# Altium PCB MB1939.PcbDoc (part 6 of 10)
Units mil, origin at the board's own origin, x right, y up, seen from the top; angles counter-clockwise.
Board outline 5910.64 x 4335.93 mil, 6 copper layers (Top Layer, l2_GND, L3_SIG, L4_VCC, L5_GND, Bottom Layer), stack 58.424 mil thick; 635 components, 489 nets, 2289 pads, 1388 vias.
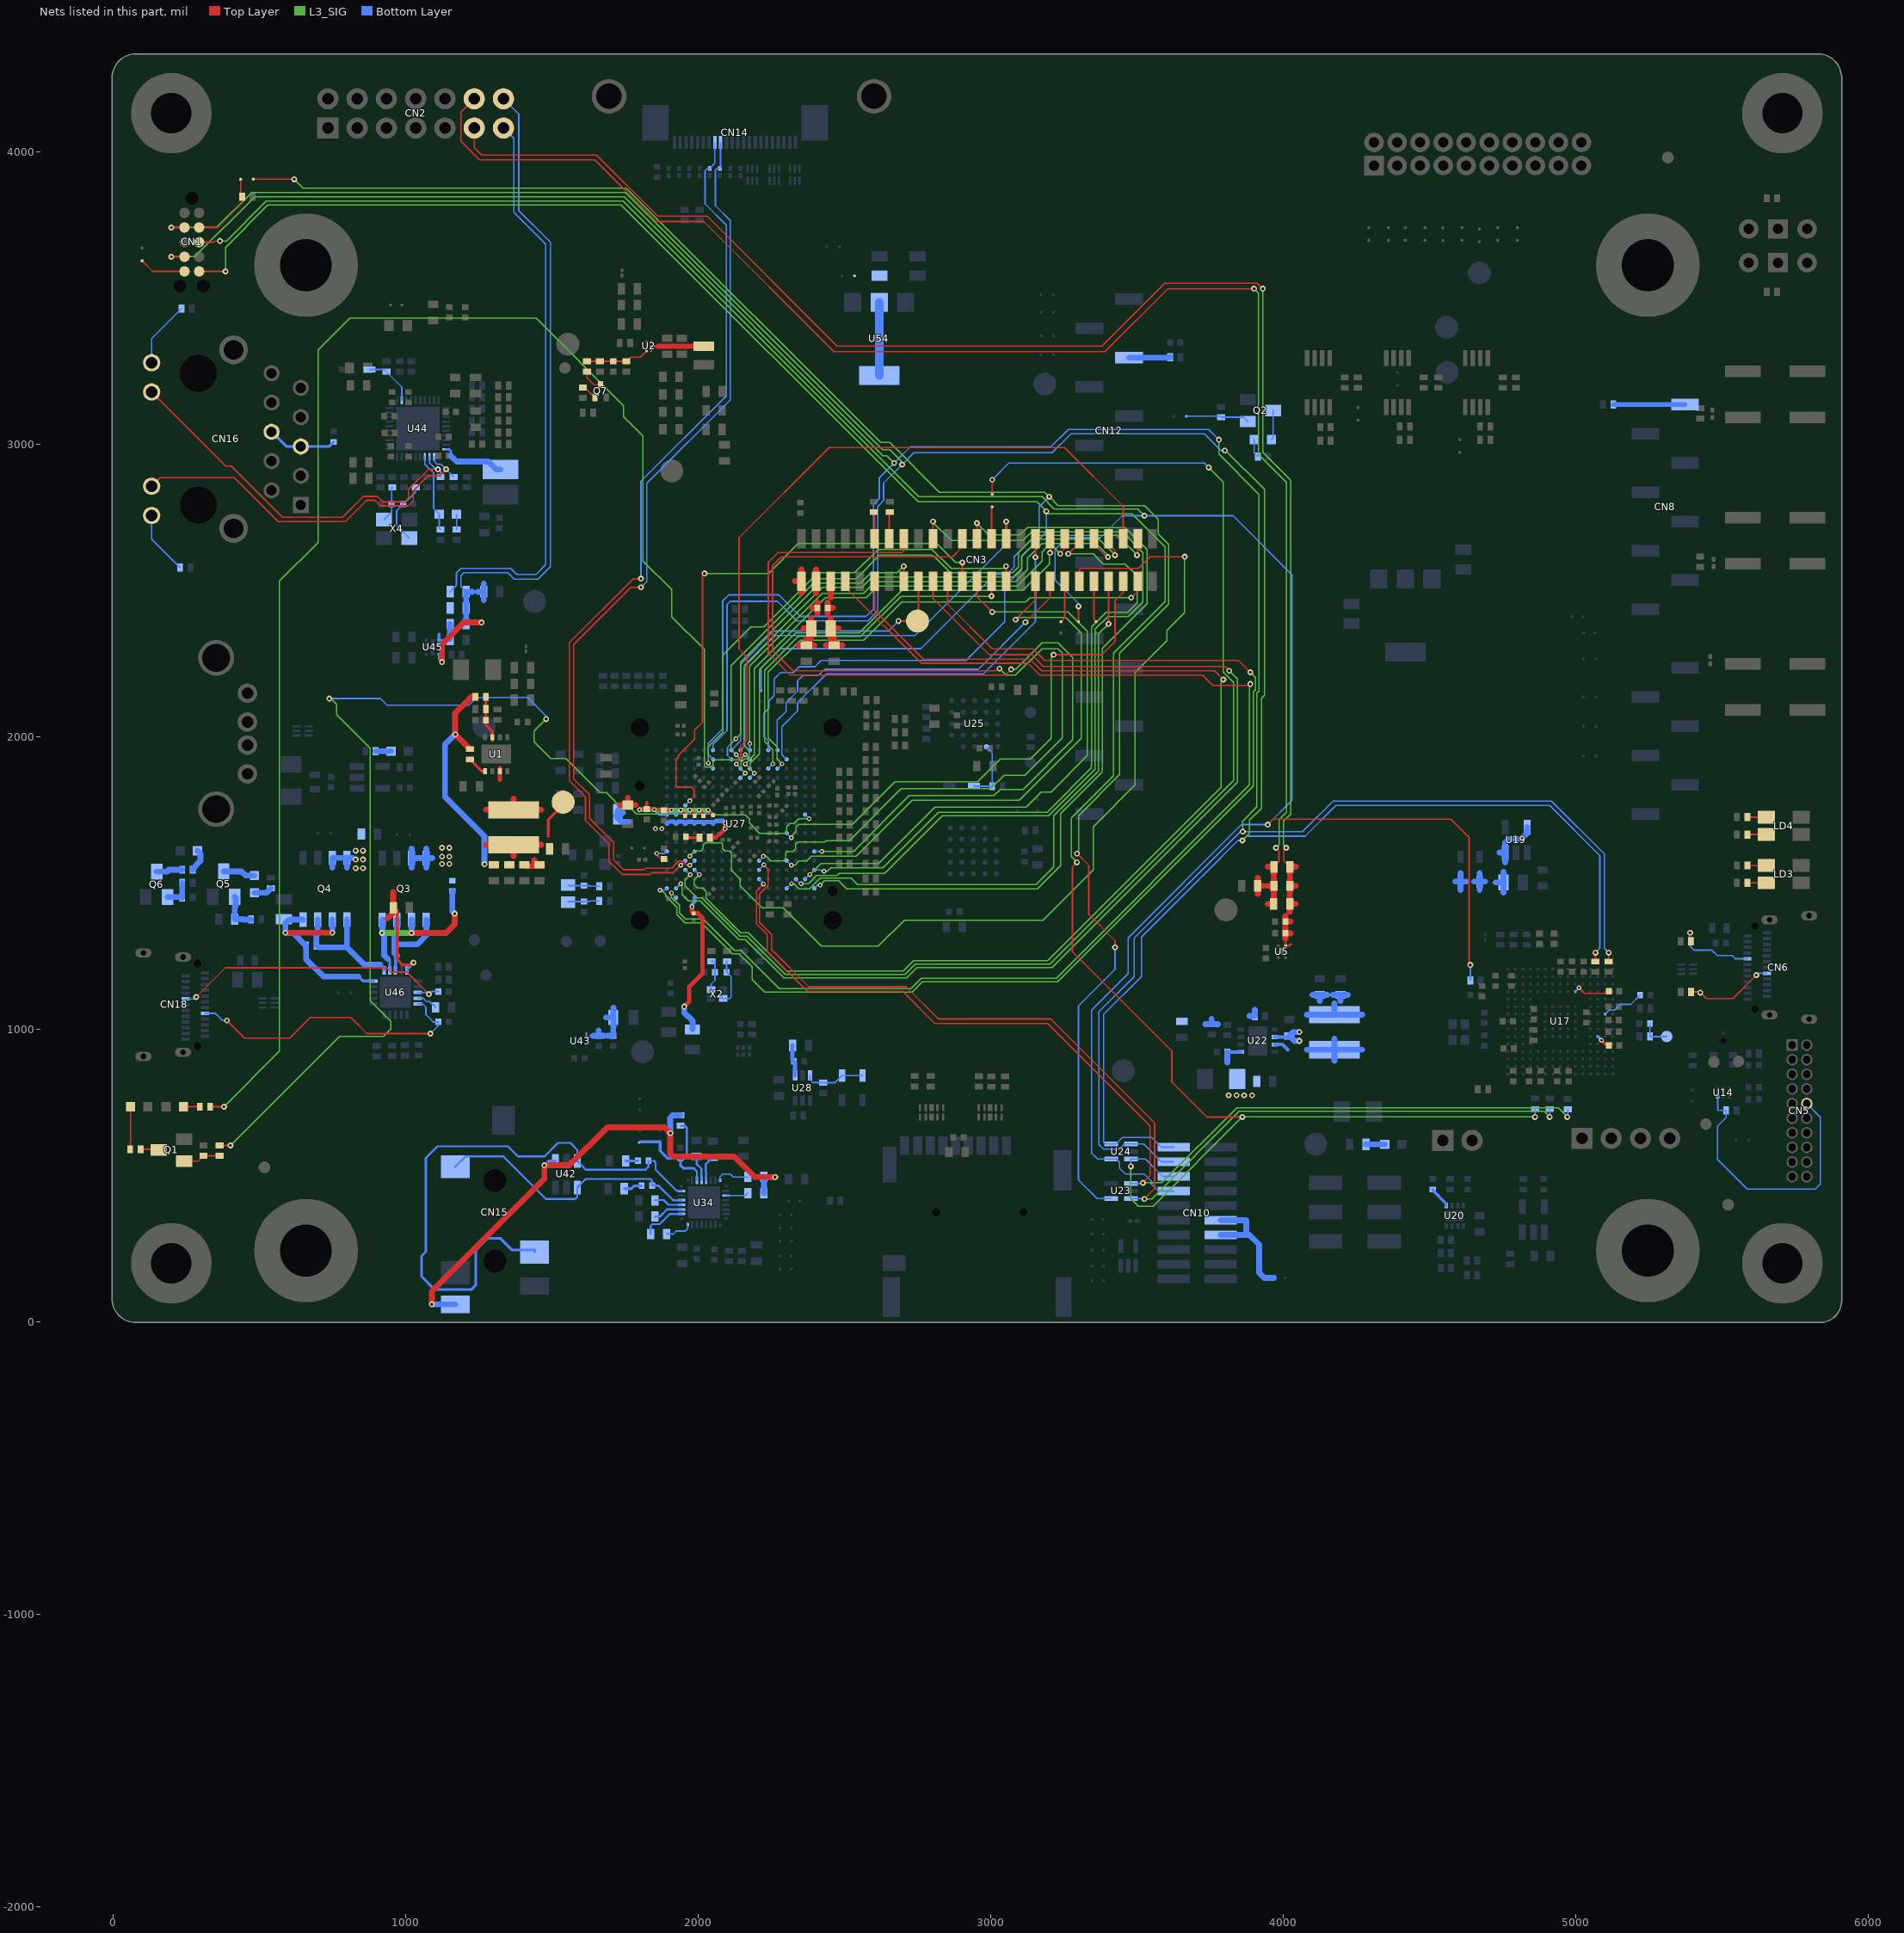
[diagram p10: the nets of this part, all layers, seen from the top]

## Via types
v1: diameter 20, hole 10, Top Layer to Bottom Layer, tented both sides, 1072 vias
v2: diameter 16, hole 8, Top Layer to Bottom Layer, tented both sides, 316 vias

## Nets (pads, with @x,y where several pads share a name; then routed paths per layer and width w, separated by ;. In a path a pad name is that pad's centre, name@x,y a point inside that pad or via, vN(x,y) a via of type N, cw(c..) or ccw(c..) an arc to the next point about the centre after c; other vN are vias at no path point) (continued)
I_SENS_VDDA1V8_N: C182.1 CN2.14 R179.1 R187.2 R188.2 U45.4 | length 2500.7
  Top Layer w20: v1(1125,2255) 1125,2316.08 1198.92,2390 v1(1260,2390)
  Bottom Layer w5: R188.2@1207.56,2495 1190,2512.56 1190,2550 1200,2560 1350,2560 1371.6,2538.4 1453,2538.4 1495,2580.4 1495,3690 1387.1,3797.9 1387.1,4127.9 CN2.14@1335,4180
  Bottom Layer w8: U45.4@1115.2,2281.57 1115.2,2264.8 v1(1125,2255)
  Bottom Layer w20: C182.1@1207.56,2402.29 R187.2@1207.56,2457.71 ; 1207.56,2467.29 R188.2@1207.56,2495 1228.18,2495 ; 1246.82,2495 R179.1@1267.45,2495 ; 1267.44,2467.29 R179.1@1267.45,2495 ; 1267.44,2522.71 R179.1@1267.45,2495
I_SENS_VDDA1V8_P: C182.2 C183.2 CN2.13 R187.1 R188.1 U45.1 U45.2 | length 2061.6
  Bottom Layer w5: R188.1@1152.45,2495 1174,2516.56 1174,2559 1190,2575 1360,2575 1380.3,2554.7 1446,2554.7 1479,2587.7 1479,3683.37 1370.28,3792.09 1370.28,4044.72 CN2.13@1335,4080
  Bottom Layer w7: U45.2@1115.2,2313.06 1131.91,2313.06
  Bottom Layer w10: 1115.19,2349.81 U45.1@1115.2,2328.81 1128.81,2328.81 1130,2330
  Bottom Layer w20: C183.2@1152.44,2335 C182.2@1152.45,2385
I_SENS_VDDIO_N: C93.1 CN2.12 R78.1 R79.2 R80.2 | length 5552.3
  Top Layer w5: CN2.12@1235,4180 1190,4135 1190,4035 1253.19,3971.81 1646.56,3971.81 1857.82,3760.55 2019.45,3760.55 2464.17,3315.83 3390.83,3315.83 3605.82,3530.82 v1(3900,3530.82) ; R80.2@3967.45,1555 3985,1572.56 3985,1610 v1(3975,1620)
  Top Layer w20: 3912.56,1462.29 R78.1@3912.56,1490 ; 3912.56,1517.71 R78.1@3912.56,1490 ; 3933.18,1490 R78.1@3912.56,1490 ; 3946.31,1427.99 R79.2@3966.94,1427.99 3966.93,1455.7 ; 3946.82,1490 C93.1@3967.45,1490 ; 3946.82,1555 R80.2@3967.45,1555 3967.44,1527.29 ; 3967.44,1464.46 C93.1@3967.45,1490 ; 3967.44,1515.54 C93.1@3967.45,1490
  L3_SIG w4: v1(3900,3530.82) 3915,3515.82 3915,2965.2 3940,2940.2 3940,2938.78 4010,2868.78 4010,1741.22 3985,1716.22 3985,1630 v1(3975,1620)
I_SENS_VDDIO_P: C93.2 C94.2 C95.2 CN2.11 R79.1 R80.1 U5.1 | length 5523.5
  Top Layer w5: CN2.11@1235,4080 1235,4012.63 1259.82,3987.81 1653.19,3987.81 1862.42,3778.58 2031.42,3778.58 2475,3335 3380,3335 3595,3550 3910.82,3550 v1(3930,3530.82) ; v1(4010,1620) 4007.49,1620 4001.49,1614 4001.49,1576.07 R80.1@4022.56,1555
  Top Layer w8: 4007.8,1297.8 U5.1@4007.8,1285.27 4020.28,1285.28 4025,1290
  Top Layer w20: 4007.21,1308.94 C94.2@4007.21,1327.99 ; 4007.21,1347.04 C94.2@4007.21,1327.99 ; 4007.21,1348.94 C95.2@4007.21,1367.99 ; 4007.21,1387.04 C95.2@4007.21,1367.99 ; 4022.05,1400.28 R79.1@4022.05,1427.99 ; 4022.05,1455.7 R79.1@4022.05,1427.99 ; 4022.56,1464.46 C93.2@4022.56,1490 ; 4022.56,1515.54 C93.2@4022.56,1490 ; 4022.56,1527.29 R80.1@4022.56,1555 4043.18,1555 ; 4025.27,1327.99 C94.2@4007.21,1327.99 ; 4025.27,1367.99 C95.2@4007.21,1367.99 ; 4042.67,1427.99 R79.1@4022.05,1427.99 ; 4043.18,1490 C93.2@4022.56,1490
  L3_SIG w4: v1(3930,3530.82) 3930,2971.27 4025,2876.27 4025,1735 4000,1710 4000,1630 v1(4010,1620)
IMU_INT1: CN14.14 U27.E4 U36.1 | length 3099.5
  Top Layer w5: v1(1805,2510) 1770,2510 1575,2315 1575,1855.44 1629,1801.44 1629,1721 1711.78,1638.22 1711.78,1579 1745.78,1545 1815,1545 1820,1550 1909.77,1550 1934.59,1574.82 1946.61,1574.82 1961.11,1560.32 v2(1972.1,1560.32)
  Bottom Layer w5: v1(1805,2510) 1825,2530 1825,2866 2109.5,3150.5 2109.5,3764.52 2059.02,3815 2059.02,3936.32 2065,3942.3 U36.1@2075,3942.31 2077.09,3944.39 CN14.14@2077.09,4030.71 ; v2(1972.1,1560.32) U27.E4@1987.81,1576.03
IMU_INT2: CN14.15 U27.E3 U37.1 | length 3097.7
  Top Layer w5: v1(1805,2540) 1778.78,2540 1560,2321.22 1560,1849.22 1615,1794.22 1615,1714 1695.78,1633.22 1695.78,1573.78 1740.56,1529 1834,1529 1840,1535 1915.28,1535 v2(1940.6,1560.32)
  Bottom Layer w5: v1(1805,2540) 1805,2873 2096.5,3164.5 2096.5,3748.5 2024.02,3820.98 2024.02,3934.02 2032.3,3942.3 U37.1@2040,3942.31 2057.4,3959.7 CN14.15@2057.41,4030.71 ; v2(1940.6,1560.32) 1956.31,1576.03 U27.E3@1956.37,1576.03
JNTRST: SB2.2 SB43.1 U23.4 | length 7593
  Top Layer w5: SB2.2@480.02,3905 v1(620,3905) ; v1(3295,1600) 3335,1560 3335,1392.5 3425,1302.5 v1(3425,1280)
  L3_SIG w4: v1(620,3905) 650,3875 1754.04,3875 2624.04,3005 2655,3005 2825,2835 3185,2835 v1(3200,2820) 3230,2790 3525,2790 3572,2743 3572,2693 3608,2657 3608,2453.01 3441,2286.01 3441,1871 3300,1730 3300,1605 v1(3295,1600)
  Bottom Layer w5: SB43.1@2215,2157.72 2215,2231.92 2283.88,2300.8 2760.8,2300.8 3015,2555 3055,2555 3080,2580 3080,2615 3165,2700 3165,2785 v1(3200,2820) ; U23.4@3412.05,421.42 3363.58,421.42 3300,485 3300,1080 3425,1205 v1(3425,1280)
LCD_B0: CN3.21 U27.R6 | length 1614.6
  Top Layer w5: v1(3052.5,2582.5) 3052.87,2582.13 CN3.21@3052.87,2531.12
  L3_SIG w4: v2(2035.01,1909.5) 2035.01,1965.01 2085,2015 2085,2280 2180,2375 2225,2375 2410,2560 2535,2560 2615,2640 2800,2640 2865,2575 3045,2575 v1(3052.5,2582.5)
  Bottom Layer w5: v2(2035.01,1909.5) 2035.01,1906.69 2050.71,1890.99 U27.R6@2050.86,1890.99
LCD_B1: CN3.23 U27.R12 | length 1286.1
  Top Layer w5: v1(3002.87,2480) CN3.23@3002.87,2531.12
  L3_SIG w4: v2(2255.48,1906.76) 2255.48,1954.75 2227,1983.23 2227,2227 2341.2,2341.2 2344.22,2341.2 2345.02,2342 2555.19,2342 2693.19,2480 v1(3002.87,2480)
  Bottom Layer w5: U27.R12@2239.84,1890.99 2255.48,1906.64 v2(2255.48,1906.76)
LCD_B2: CN3.25 U27.C16 | length 2043.1
  Top Layer w5: CN3.25@2952.87,2531.12 2952.87,2478.13 v1(3005,2426)
  L3_SIG w4: v2(2381.48,1528.79) 2419.69,1567 2617,1567 2809,1759 3120.99,1759 3173,1811.01 3206.01,1811.01 3330,1935 3330,2360 3264,2426 v1(3005,2426)
  Bottom Layer w5: U27.C16@2365.82,1513.03 2365.82,1513.13 v2(2381.48,1528.79)
LCD_B3: CN3.27 U27.L3 | length 1912.4
  Top Layer w5: v2(1972,1780.63) 1987,1795.63 1987,1816.73 1976.12,1827.61 1930,1827.61 1924.7,1832.91 1924.7,1920.62 1932.53,1928.45 1932.53,1935.53 1988,1991 1988,2021.99 2015,2048.99 2015,2550.5 v1(2022.1,2557.6) ; CN3.27@2902.87,2531.12 v1(2902.87,2595)
  L3_SIG w4: v1(2022.1,2557.6) 2240.4,2557.6 2342.8,2660 2815,2660 2880,2595 v1(2902.87,2595)
  Bottom Layer w5: U27.L3@1956.37,1765 v2(1972,1780.63)
LCD_B4: CN3.29 U27.B1 | length 4141.1
  Top Layer w5: CN3.29@2852.87,2531.12 2852.87,2452.13 3005,2300 3145,2300 3185,2260 3847,2260 v1(3887,2220)
  L3_SIG w4: v2(1869.89,1475.41) 1874.36,1475.41 1888.95,1460.82 1888.95,1456.05 1928,1417 1928,1392 1956,1364 2012,1364 2118,1258 2140,1258 2185,1213 2185,1170 2228,1127 2732,1127 2767.59,1162.59 3229.22,1162.59 3897,1830.37 3897,2152.95 3905,2160.95 3905,2202 v1(3887,2220)
  Bottom Layer w5: v2(1869.89,1475.41) 1870,1475.52 1887.36,1475.52 U27.B1@1893.38,1481.54
LCD_B5: CN3.31 U27.B2 | length 3920.4
  Top Layer w5: CN3.31@2802.87,2531.12 2802.87,2472.13 2995,2280 3140,2280 3180,2240 3800,2240 v1(3815,2225)
  L3_SIG w4: v2(1940.5,1497.26) 1945,1492.76 1945,1460.01 1967.01,1438 2007.01,1438 2139.01,1306 2162,1306 2293,1175 2711.99,1175 2747.58,1210.59 3209.3,1210.59 3843,1844.29 3843,2197 v1(3815,2225)
  Bottom Layer w5: U27.B2@1924.88,1481.54 1924.87,1481.63 v2(1940.5,1497.26)
LCD_B6: CN3.33 TP1.1 U27.U8 | length 1109.8
  Top Layer w5: v1(2685,2395) TP1.1@2750,2395 2752.87,2397.87 CN3.33@2752.87,2531.12
  Bottom Layer w5: U27.U8@2113.85,1953.98 2145,1985.13 2145,2093.89 2145.03,2209.04 2145.03,2247.47 2257.86,2360.3 2258.5,2360.3 2259,2360.8 2650.8,2360.8 v1(2685,2395)
LCD_B7: CN3.35 U27.T8 | length 1101.1
  Top Layer w5: CN3.35@2702.87,2531.12 v1(2702.87,2582.13)
  L3_SIG w4: v2(2129.5,1993.1) 2144.62,2008.22 2144.62,2254.62 2415,2525 2555,2525 2590,2560 2680.74,2560 v1(2702.87,2582.13)
  Bottom Layer w5: U27.T8@2113.85,1922.48 2100.2,1936.13 2100.2,1963.8 v2(2129.5,1993.1)
LCD_BL_CTRL: CN3.43 U27.A2 | length 4337.1
  Top Layer w5: CN3.43@2502.87,2531.12 2502.87,2510.91 2762.78,2251 3126.56,2251 3167.56,2210 3724,2210 3759,2175 3880,2175 3885,2180 v1(3887,2180)
  L3_SIG w4: v2(1909.02,1465.8) 1909.02,1450.98 1936.5,1423.5 1936.5,1397.5 1957,1377 2017,1377 2124,1270 2147.06,1270 2278.06,1139 2726.93,1139 2762.52,1174.59 3224.24,1174.59 3885,1835.35 3885,2178 v1(3887,2180)
  Bottom Layer w5: v2(1909.02,1465.8) 1924.78,1450.04 U27.A2@1924.88,1450.04
LCD_CLK: CN3.32 U27.C15 | length 2886.9
  Top Layer w5: CN3.32@2802.87,2676.22 v1(2802.87,2735)
  L3_SIG w4: v2(2351.9,1497.3) 2376.96,1497.3 2404.66,1525 2475,1525 2483,1533 2638,1533 2835,1730 3198.02,1730 3356,1887.98 3356,1895.01 3356.97,1895.98 3356.97,1902.97 ; v1(2802.87,2735) 2802.87,2732.13 2865,2670 3110,2670 3140,2700 3450,2700 3520,2630 3520,2460 3470,2410 3400,2410 3357,2367 3357,1903
  Bottom Layer w5: U27.C15@2334.33,1513.03 2350.02,1497.3 v2(2351.9,1497.3)
LCD_DE: CN3.22 U27.U9 | length 1494.9
  Top Layer w5: CN3.22@3052.87,2676.22 v1(3052.87,2735)
  Bottom Layer w5: U27.U9@2145.35,1953.98 2160,1968.64 2160,2087.67 2160.03,2209.03 2160.03,2241.25 2259.08,2340.3 2259.72,2340.3 2265.22,2345.8 2741.2,2345.8 3052.87,2657.47 v1(3052.87,2735)
LCD_G0: CN3.4 U27.T9 | length 2070.2
  Top Layer w5: v1(3500,2620) 3502.87,2622.87 CN3.4@3502.87,2676.22
  L3_SIG w4: v2(2130.62,1938.6) 2112.6,1956.62 2112.6,2242.6 2410,2540 2540,2540 2620,2620 2800,2620 2805,2615 2808.02,2615 2863.02,2560 3075,2560 3095,2580 3095,2630.01 3152.99,2688 3432,2688 v1(3500,2620)
  Bottom Layer w5: v2(2130.62,1938.6) 2130.62,1937.14 U27.T9@2145.35,1922.48 U27.T9@2145.35,1922.48
LCD_G1: CN3.6 U27.R9 | length 2456
  Top Layer w5: v2(2130.26,1906.07) 2146,1921.81 2146,1968.9 2167.12,1990.02 2167.12,2272.12 2140,2299.24 2140,2680 2447.67,2987.67 3252.33,2987.67 3452.87,2787.13 CN3.6@3452.87,2676.22
  Bottom Layer w5: v2(2130.26,1906.07) U27.R9@2145.35,1890.99
LCD_G2: CN3.8 U27.P9 | length 1979.5
  Top Layer w5: CN3.8@3402.87,2676.22 3402.87,2657.13 3425,2635 v1(3425,2620)
  L3_SIG w4: v2(2160.99,1875.27) 2146.8,1889.46 2146.8,1912.54 2158.39,1924.13 2166.87,1924.13 2175.07,1932.33 2175.07,1951.62 2156.62,1970.07 2156.62,2238.6 2160,2241.98 2160,2245 2425,2510 2560,2510 2595,2545 3076.98,2545 3107,2575.02 3107,2617 3165,2675 3370,2675 v1(3425,2620)
  Bottom Layer w5: U27.P9@2145.35,1859.49 2145.34,1859.62 v2(2160.99,1875.27)
LCD_G3: CN3.10 U27.U10 | length 1815.5
  Top Layer w5: CN3.10@3352.87,2676.22 3352.87,2657.14 3396.08,2613.93 v1(3400.74,2613.93)
  L3_SIG w4: v2(2176.78,1976.01) 2176.78,2241.78 2425,2490 2565,2490 2605,2530 3085,2530 3125,2570 3125,2610 3175,2660 3360,2660 3400.74,2619.26 v1(3400.74,2613.93)
  Bottom Layer w5: v2(2176.78,1976.01) 2176.84,1975.95 U27.U10@2176.84,1953.98
LCD_G4: CN3.12 U27.D17 | length 2192.2
  Top Layer w5: v1(3265,2625) 3302.87,2662.87 CN3.12@3302.87,2676.22
  L3_SIG w4: v2(2430,1540) 2441.51,1540 2453.51,1552 2632,1552 2822,1742 3193.04,1742 3344,1892.96 3344,1899.99 3344.97,1900.96 3344.97,1907.95 ; v1(3265,2625) 3350,2625 3385,2590 3460,2590 3500,2550 3500,2456.98 3468.02,2425 3395,2425 3345,2375 3345,1907.98
  Bottom Layer w5: U27.D17@2397.32,1544.53 2419,1544.53 2423.53,1540 v2(2430,1540)
LCD_G5: CN3.14 U27.R10 | length 1667.6
  Top Layer w5: v1(3237.5,2625) 3235,2625 3252.87,2642.87 CN3.14@3252.87,2676.22
  L3_SIG w4: v2(2161.32,1906.51) 2192.48,1937.67 2192.48,2232.48 2435,2475 2575,2475 2615,2515 3090,2515 3175,2600 3175,2631 3192,2648 3216,2648 3220,2644 3220,2642.5 v1(3237.5,2625)
  Bottom Layer w5: v2(2161.32,1906.51) U27.R10@2176.84,1890.99
LCD_G6: CN3.16 U27.P10 | length 1623.3
  Top Layer w5: v1(3202.5,2628.25) 3202.87,2628.62 CN3.16@3202.87,2676.22
  L3_SIG w4: v2(2192.49,1875.27) 2177.4,1890.36 2177.4,1909.2 2210,1941.8 2210,2230 2333.7,2353.7 2339.74,2353.7 2340.04,2354 2550.21,2354 2696.21,2500 3110,2500 3200,2590 3200,2625.75 v1(3202.5,2628.25)
  Bottom Layer w5: U27.P10@2176.84,1859.49 2176.84,1859.62 v2(2192.49,1875.27)
LCD_G7: CN3.18 U27.T14 | length 1433.5
  Top Layer w5: v1(3152.87,2612.87) CN3.18@3152.87,2676.22
  Bottom Layer w5: U27.T14@2302.83,1922.48 U27.T14@2302.83,1922.48 2286.52,1938.72 2286.52,2034.42 2340,2087.9 2340,2116.22 2438.78,2215 2975,2215 3152.87,2392.87 v1(3152.87,2612.87)
LCD_HSYNC: CN3.26 U27.B17 | length 2794.1
  Top Layer w5: CN3.26@2952.87,2676.22 v1(2952.87,2730)
  L3_SIG w4: v2(2417.5,1492.5) 2432.51,1507.51 2480.49,1507.51 2508,1480 3160,1480 3238.47,1558.47 3238.47,1736.49 3380,1878.02 3380,1885.05 3380.97,1886.02 3380.97,1893.01 ; v1(2952.87,2730) 2992.87,2690 3100,2690 3125,2715 3460,2715 3535,2640 3535,2455 3381,2301 3381,1893.04
  Bottom Layer w5: U27.B17@2397.32,1481.54 2408.27,1492.5 v2(2417.5,1492.5)
LCD_INT: CN3.39 U27.D4 | length 4023.7
  Top Layer w5: CN3.39@2602.87,2531.12 2602.87,2432.13 2770,2265 3133.78,2265 3173.78,2225 3765,2225 v1(3795,2195)
  L3_SIG w4: v2(2003.7,1528.69) 1986.12,1511.11 1986.12,1494.96 1998.08,1483 2015.65,1483 2028,1470.65 2028,1447 2145,1330 2152.04,1330 2171.95,1330.01 2302.96,1199 2700.99,1199 2736.58,1234.59 3194.34,1234.59 3787,1827.25 3787,2191 3791,2195 v1(3795,2195)
  Bottom Layer w5: U27.D4@1987.87,1544.53 v2(2003.7,1528.69)
LCD_NRST: CN3.36 U27.F17 | length 3288.8
  Top Layer w5: CN3.36@2702.87,2676.22 2702.87,2635.87 2696,2629 2274,2629 2240,2595 2240,2285 2315,2210 3050,2210 v1(3070,2230)
  L3_SIG w4: v2(2422.52,1607.5) 2531.5,1607.5 2722,1798 3011,1798 3033,1820 3110.32,1820 3280,1989.68 3280,2270 3230,2320 3175,2320 3085,2230 v1(3070,2230)
  Bottom Layer w5: U27.F17@2397.32,1607.52 v2(2422.52,1607.5)
LCD_ON/OFF: SB5.2 U27.D3 | length 4268.7
  Top Layer w5: SB5.2@3005,2828.62 v1(3005,2878)
  L3_SIG w4: v2(1972.95,1528.5) 1972.95,1527.95 1955,1510 1955,1490 1996,1449 2012.99,1449 2143.99,1318 2157.02,1318 2166.97,1318.01 2297.98,1187 2707.01,1187 2742.6,1222.59 3202.6,1222.59 3830,1849.99 3830,2185 3795,2220 3795,2870 v1(3745,2920)
  Bottom Layer w5: U27.D3@1956.37,1544.53 1972.4,1528.5 v2(1972.95,1528.5) ; v1(3005,2878) 3062,2935 3730,2935 v1(3745,2920)
LCD_R0: CN3.3 U27.R13 | length 1766.2
  Top Layer w5: v1(3480,2475) 3502.87,2497.87 CN3.3@3502.87,2531.12
  L3_SIG w4: v2(2286.97,1906.76) 2270,1923.73 2270,1965 2240,1995 2240,2220 2350,2330 2566.1,2330 2696.1,2460 3119.99,2460 3134.99,2475 v1(3480,2475)
  Bottom Layer w5: U27.R13@2271.33,1890.99 2271.33,1891.12 v2(2286.97,1906.76)
LCD_R1: CN3.5 U27.H14 | length 1797.8
  Top Layer w5: v1(3215,2280) 3380.01,2280 3425,2324.99 3425,2465.01 3452.87,2492.88 CN3.5@3452.87,2531.12
  L3_SIG w4: v2(2318.52,1654.79) 2318.52,1659.51 2335.55,1676.54 2335.55,1691.59 2344.25,1700.29 2527.29,1700.29 2673,1846 2955,1846 3033,1924 3136,1924 3206,1994 3206,2271 v1(3215,2280)
  Bottom Layer w5: U27.H14@2302.83,1670.51 v2(2318.52,1654.79)
LCD_R2: CN3.7 U27.B14 | length 2029.7
  Top Layer w5: v1(3402.87,2385) CN3.7@3402.87,2531.12
  L3_SIG w4: v2(2319.4,1498) 2327,1498 2345,1480 2380,1480 2417,1517 2523,1517 2545,1495 3155,1495 3215,1555 3215,1730 3368,1883 3368,1890.03 3368.97,1891 3368.97,1897.99 ; 3369,1898.02 3369,2351.13 v1(3402.87,2385)
  Bottom Layer w5: U27.B14@2302.83,1481.54 2319.28,1498 v2(2319.4,1498)
LCD_R3: CN3.9 SB8.1 | length 141
  Top Layer w5: CN3.9@3352.87,2531.12 3352.87,2400.17 SB8.1@3360,2393.04
LCD_R4: CN3.11 U27.F4 | length 3356.1
  Top Layer w5: CN3.11@3302.87,2531.12 3302.87,2570 3307.87,2575 3505,2575 3545,2615 v1(3663,2615)
  L3_SIG w4: v2(1972.1,1591.82) 1989.28,1609 2009.08,1609 2009.31,1609.23 2009.39,1609.23 2017.59,1617.43 2017.59,1629.08 2025.8,1637.29 2080.01,1637.29 2084.06,1633.24 2084.06,1617.48 2092.26,1609.28 2108.02,1609.28 2115,1602.3 2115,1543 2144,1514 2144,1490 2219,1415 2290,1415 2421,1284 2615.98,1284 2704.98,1373 3178.87,1373 3350,1544.13 3350,1692 3493,1835 3493,2218.95 3602,2327.95 3602,2362.98 3663,2423.98 v1(3663,2615)
  Bottom Layer w5: v2(1972.1,1591.82) 1987.8,1607.52 U27.F4@1987.87,1607.52
LCD_R5: CN3.13 SB6.1 | length 143.7
  Top Layer w5: SB6.1@3240,2392.72 3252.87,2405.59 CN3.13@3252.87,2531.12
LCD_R6: CN3.15 U27.U13 | length 1302.7
  Top Layer w5: v1(3118.94,2391) 3118.94,2391.07 3202.87,2475 CN3.15@3202.87,2531.12
  Bottom Layer w5: U27.U13@2271.33,1953.98 2270.52,1954.79 2270.52,2055.77 2301,2086.25 2301,2116 2340,2155 2340,2190.81 2357.93,2208.74 2411.3,2208.74 2432.56,2230 2957.87,2230 v1(3118.94,2391) v1(3118.94,2391)
LCD_R7: CN3.17 U27.E14 | length 1963.3
  Top Layer w5: v1(3085,2400) 3152.87,2467.87 CN3.17@3152.87,2531.12
  L3_SIG w4: v2(2318.52,1560.3) 2331.3,1560.3 2336.02,1565.02 2336.02,1566.1 2344.22,1574.3 2345.3,1574.3 2346,1575 2371.01,1575 2388.01,1592 2541,1592 2732,1783 3098.04,1783 3310,1994.96 3310,2354 3256,2408 3093,2408 v1(3085,2400)
  Bottom Layer w5: U27.E14@2302.83,1576.03 v2(2318.52,1560.3)
LCD_VSYNC: CN3.28 U27.E11 | length 3598.9
  Top Layer w5: CN3.28@2902.87,2676.22 2902.87,2647.87 2870,2615 2285,2615 2255,2585 2255,2295 2325,2225 3020,2225 3027.5,2232.5 v1(3030,2232.5)
  L3_SIG w4: v2(2223.16,1590.85) 2233.15,1590.85 2248.4,1575.6 2291.6,1575.6 2300,1584 2300,1601 2306,1607 2325,1607 2334,1616 2334,1632 2342,1640 2433.92,1640 2439,1645.08 2517.08,1645.08 2694,1822 2999.94,1822 3045.94,1868 3117,1868 3245,1996 3245,2285 3229.85,2300.15 3175.15,2300.15 3085,2210 3052.5,2210 v1(3030,2232.5)
  Bottom Layer w5: U27.E11@2208.34,1576.03 v2(2223.16,1590.85)
LED1: R4.2 U27.K16 | length 3987.2
  Top Layer w5: R4.2@365,602.72 v1(402.28,602.72)
  L3_SIG w4: v1(402.28,602.72) 774.56,975 925,975 950,1000 950,1027 880,1097 880,1960 765,2075 765,2110 745,2130 v1(740,2130) ; v1(1481,2060) 1439.5,2018.5 1439.5,1982 1496.75,1924.75 1548.25,1924.75 1664,1809 1686,1809 1743,1752 1773,1752 1789.9,1735.1 2057.9,1735.1 2060,1733 2161,1733 2176,1718 2176,1704 2210,1670 2295,1670 2303,1678 2303,1691 2314.8,1702.8 2327.5,1702.8 2344.36,1719.66 v2(2379.67,1719.66)
  Bottom Layer w5: v1(740,2130) 915,2130 937.4,2107.6 1216.7,2107.6 1242.6,2133.5 1417.3,2133.5 1481,2069.8 v1(1481,2060) ; U27.K16@2365.82,1733.51 v2(2379.67,1719.66)
LED2: R2.1 U27.T10 | length 5514.5
  Top Layer w5: R2.1@332.72,735 v1(380,735)
  L3_SIG w4: v1(380,735) 570,925 570,2532 701.5,2663.5 701.5,3321.5 810,3430 1446.48,3430 1745.9,3130.58 1745.9,3094 1812,3027.9 1812,2600.5 1910,2502.5 1910,2409 2021.01,2297.99 2021.01,1900.89 2026.7,1895.2 2046.5,1895.2 2051.4,1900.1 2051.4,1913.9 2058.5,1921 2143.94,1921 v2(2161.07,1938.13)
  Bottom Layer w5: v2(2161.07,1938.13) 2176.72,1922.48 U27.T10@2176.84,1922.48
MCU.JTDI: CN1.8 CN10.8 R122.2 SB7.1 U24.4 | length 8831.3
  Top Layer w5: CN1.8@295.02,3690 344.77,3690 348.77,3694 v1(366.27,3694) ; SB7.1@3300,2393.04 v1(3300,2445) ; v1(3946.63,1699.3) 3964.83,1717.5 4572.51,1717.5 4635,1655.01 4635,1223.97 v1(4638.97,1220)
  L3_SIG w4: v1(366.27,3694) 388.21,3694 524.21,3830 1744.31,3830 2754.31,2820 3175,2820 3217,2778 3502,2778 v1(3525,2755)
  Bottom Layer w5: v1(3300,2445) 3300,2455 3220,2535 3220,2640 3260,2680 3375,2680 3450,2755 v1(3525,2755) 3828,2755 4030,2553 4030,1782.67 v1(3946.63,1699.3) 3856.75,1699.3 3470,1312.55 3470,1190 3345,1065 3345,576.42 3365,556.42 3428.57,556.42 3440,544.99 3440,525 3460,505 3525,505 3550,480 3550,470 3572.99,447.01 CN10.8@3625.53,447.01 ; R122.2@4638.98,1166.42 v1(4638.97,1220)
MCU.SWCLK: CN1.4 CN10.4 R95.2 U24.1 U27.T6 | length 10529.8
  Top Layer w5: v1(200,3640) CN1.4@245.02,3640 ; R95.2@5111.69,1231.42 v1(5111.69,1261.69)
  L3_SIG w4: v1(200,3640) 280,3640 485,3845 1747.55,3845 2631.84,2960.71 2644.29,2960.71 v1(2670,2935) ; v1(3779.65,3015) 3779.65,2965.35 3917,2828 3917,2155.97 3910,2148.97 3910,1760 3861.11,1711.11 v1(3861.11,1675)
  Bottom Layer w5: U27.T6@2050.86,1922.48 2050.79,1922.48 2035,1938.27 2035,1977 2083.83,2025.83 2083.87,2085 2083.96,2215.29 2083.96,2463.66 2105,2484.7 2275.8,2484.7 2349.45,2411.05 2574.06,2411.05 2599.05,2436.04 2599.05,2793.04 2619,2812.99 2619,2884 v1(2670,2935) 2725,2990 3205,2990 3265,3050 3744.65,3050 v1(3779.65,3015) ; CN10.4@3625.53,547.01 3582.99,547.01 3522.4,607.6 3457.6,607.6 3440,590 3385,590 3370,605 3370,1060 3490,1180 3490,1311.33 3853.67,1675 v1(3861.11,1675) 4065,1675 4170,1780 4916.22,1780 5096.69,1599.53 5096.69,1276.69 v1(5111.69,1261.69)
MCU.SWDIO: CN1.2 CN10.2 R94.2 U24.5 U27.U6 | length 10397.8
  Top Layer w5: v1(200,3740) CN1.2@245.02,3740 ; R94.2@5066.69,1231.42 v1(5066.69,1261.69)
  L3_SIG w4: v1(200,3740) 355,3740 475,3860 1750.8,3860 2630.8,2980 2655,2980 2697.5,2937.5 v1(2697.5,2930) ; v1(3800,2977.5) 3802.5,2977.5 3935.1,2844.9 3935.1,2141.2 3925,2131.1 3925,1755 3885,1715 3885,1670 v1(3860,1645)
  Bottom Layer w5: U27.U6@2050.86,1953.98 2050.79,1954.05 2050.79,1972.79 2098.89,2020.89 2098.93,2085 2099.01,2215.28 2099.01,2451.21 2110.5,2462.7 2271,2462.7 2337.7,2396 2580.3,2396 2614.1,2429.8 2614.1,2786.8 2634.05,2806.75 2634.05,2866.55 v1(2697.5,2930) 2737.5,2970 3210,2970 3275,3035 3730,3035 3787.5,2977.5 v1(3800,2977.5) ; CN10.2@3625.53,597.01 3582.99,597.01 3550,630 3450.01,630 3427.61,607.6 3392.67,607.6 3386,614.27 3386,1051.01 3515,1180.01 3515,1315 3712.5,1512.5 3712.5,1512.61 3732.39,1532.5 3732.5,1532.5 3845,1645 v1(3860,1645) 3875,1660 4074.76,1660 4179.76,1765 4910,1765 5081.69,1593.31 5081.69,1276.69 v1(5066.69,1261.69)
MCU.SWO: CN1.6 CN10.6 R116.2 U24.3 U27.U12 | length 9754.9
  Top Layer w5: CN1.6@295.02,3590 v1(385,3590) ; v1(3294.48,1570.52) 3294.48,1569.48 3279.48,1554.48 3279.48,1265.51 3619,925.99 3619,820 3739,700 v1(3860,700)
  L3_SIG w4: v1(385,3590) 385,3672.04 530.06,3817.1 1736.95,3817.1 2752.01,2802.04 3157.96,2802.04 v1(3190,2770) 3198,2762 3483,2762 3596,2649 3596,2461 3420,2285 3420,1866.98 3275,1721.98 3275,1590 v1(3294.48,1570.52) ; v1(3478.97,531.03) 3478.97,421.03 3505,395 3555,395 v1(3860,700) v1(4860,700)
  Bottom Layer w5: U27.U12@2239.84,1953.98 2239.83,1985.18 2225,2000.01 2225,2080 2242,2097 2242,2122.01 2260,2140.01 2260,2196.6 2282.6,2219.2 2325.95,2219.2 2345.49,2238.74 2398.86,2238.74 2420.12,2260 2915,2260 3047.5,2392.5 3047.5,2512.5 3105,2570 3105,2615 3190,2700 v1(3190,2770) ; v1(3478.97,531.03) U24.3@3478.98,556.42 3528.59,556.42 3588,497.01 CN10.6@3625.53,497.01 ; v1(4860,700) R116.2@4860,727.28
MCU.VCP_RX: R114.2 U23.3 U27.D11 | length 3768.7
  Top Layer w5: v2(2225,1562) 2239.68,1547.32 2239.68,1491.84 2210,1462.16 2210,1365 2251.06,1323.94 2251.06,1272.48 2378.04,1145.5 2710.5,1145.5 2821,1035 3205,1035 3560,680 3560,455 v1(3525,420)
  L3_SIG w4: v1(3525,420) 3550,420 3849,719 4891,719 v1(4910,700)
  Bottom Layer w5: U27.D11@2208.34,1544.53 2208.34,1545.34 v2(2225,1562) ; U23.3@3478.98,421.42 3523.58,421.42 v1(3525,420) ; v1(4910,700) R114.2@4910,727.28
MCU.VCP_TX: R112.2 U23.1 U27.C11 | length 3676.6
  Top Layer w5: v2(2223.66,1496.33) 2200,1472.67 2200,1360 2236,1324 2236,1318.94 2236.06,1318.88 2236.06,1266.26 2372.64,1129.68 2699.32,1129.68 2809,1020 3195,1020 3545,670 3545,500 v1(3520,475)
  L3_SIG w4: v1(3520,475) 3585,475 3841,731 4939.39,731 v1(4970.2,700.19)
  Bottom Layer w5: U27.C11@2208.34,1513.03 2223.66,1497.71 v2(2223.66,1496.33) ; U23.1@3478.98,472.6 3517.6,472.6 v1(3520,475) ; v1(4970.2,700.19) 4971.69,701.7 R112.2@4971.69,725.98
MIC: C154.2 C156.2 CN15.2 R156.1 U42.4 | length 1896.1
  Top Layer w20: v1(1090,60) 1090,105 1475,490 v1(1475,535) 1560,535 1690,665 1885,665 v1(1905,645) 1905,575 1915,565 2123.7,565 2193.7,495 v1(2263.39,495)
  Bottom Layer w10: v1(1475,535) 1489.78,549.78 U42.4@1512.6,549.78
  Bottom Layer w20: v1(1090,60) 1090.47,59.53 CN15.2@1170.01,59.53 ; v1(1905,645) 1905,697.5 1912.93,705.43 R156.1@1940,705.43 ; C154.2@2225.12,440 C156.2@2225.12,495 v1(2263.39,495)
MIC_DET: CN5.10 R105.1 U14.6 | length 949.8
  Bottom Layer w5: U14.6@5484.16,771.35 5484.16,725.84 5487,723 R105.1@5513.25,723 5513.25,698.25 5484,669 5484,555 5585,454 5818,454 5835,471 5835,699.62 CN5.10@5788.72,745.9
NetC20_2: C20.2 R10.2 R11.1 U1.3 | length 158.2
  Top Layer w10: R11.1@1275.44,2136 1275.44,2057.72 1275,2057.28 1275,2040 1297.2,2017.8 1297.2,1987.3 1297.14,1987.24
NetC21_2: C21.2 C22.2 C25.2 C26.2 L3.2 R8.2 R11.2 R21.1 TP14.1 | length 1190.6
  Top Layer w10: 1488,1659 1488,1716 1539,1767 TP14.1@1539,1776
  Top Layer w20: R8.2@1220,1957.72 v1(1170,2007.72) 1170,2080 1226,2136 R11.2@1239.28,2136 ; 1275.36,1629.96 L3.2@1370,1629.96 ; 1370,1592.41 L3.2@1370,1629.96 ; C25.2@1412.29,1557.56 1440,1557.56 ; 1440,1578.18 1440,1557.56 ; 1464.64,1629.96 L3.2@1370,1629.96 ; C26.2@1467.71,1557.56 1440,1557.56
  Bottom Layer w20: v1(1170,2007.72) 1135,1972.72 1135,1795 1270,1660 v1(1270,1564)
NetC29_2: C29.2 C35.2 C41.2 C45.2 C48.2 C52.2 L4.2 U27.K1 U27.K2 U27.K3 U27.K4 U27.K5 U27.K6 | length 827
  Top Layer w10: v2(1800,1750) 1802.72,1752.72 C29.2@1825,1752.72 ; 1825,1775 C29.2@1825,1752.72 ; v2(1909.08,1749.21) 1908.58,1748.72 C35.2@1884,1748.72 1882.96,1749.76 1851.54,1749.76 v2(1850.5,1750.8) 1848.58,1752.72 C29.2@1825,1752.72 ; v2(1940.58,1749.22) 1956,1733.8 C41.2@1956,1728.65 ; v2(1972.08,1749.22) 1988,1733.3 C45.2@1988,1728.83 ; v2(2003.57,1749.22) 2018,1734.79 C48.2@2018,1728.83 ; v2(2035.07,1749.22) 2033.57,1747.72 2034.11,1747.72 C52.2@2051,1730.83
  Top Layer w20: 1733.28,1766.5 L4.2@1760,1766.5 ; 1760,1790.27 L4.2@1760,1766.5 ; 1786.72,1766.5 L4.2@1760,1766.5
  L3_SIG w15: v2@1800,1750.61 1850.31,1750.61 v2(1850.5,1750.8) 1852.09,1749.21 v2(1909.08,1749.21) ; v2(1909.08,1749.21) v2(1940.58,1749.22) v2(1972.08,1749.22) v2(2003.57,1749.22) v2(2035.07,1749.22)
  Bottom Layer w10: v2(1850.5,1750.8) 1867.8,1733.5 U27.K1@1893.38,1733.51 v2(1909.08,1749.21) 1909.17,1749.21 U27.K2@1924.88,1733.51 v2(1940.58,1749.22) U27.K3@1956.29,1733.51 ; U27.K4@1987.79,1733.51 v2(1972.08,1749.22) U27.K3@1956.37,1733.51 ; U27.K4@1987.85,1733.5 v2(2003.57,1749.22) v2(2003.57,1749.22) U27.K5@2019.36,1733.51 v2(2035.07,1749.22) 2050.78,1733.51 U27.K6@2050.86,1733.51 ; U27.K3@1956.3,1733.51 U27.K3@1956.37,1733.51 ; U27.K3@1956.29,1733.51 U27.K3@1956.37,1733.51
NetC30_1: C30.1 R28.1 R29.2 R157.2 U2.C1 | length 219.1
  Top Layer w5: R157.2@1620,3282.72 R28.1@1665,3282.72 C30.1@1710,3282.72 R29.2@1755,3282.72 1769.28,3297 1802.75,3297 U2.C1@1824.25,3318.5
NetC34_2: C34.2 U27.F1 | length 69.6
  Top Layer w5: v2(1859,1601) 1859,1596 1872.72,1582.28 C34.2@1880,1582.28
  Bottom Layer w5: v2(1859,1601) 1884.86,1601 1885.86,1600 U27.F1@1893.38,1607.52
NetC37_2: C37.2 R220.1 | length 53.5
  Top Layer w10: C37.2@1958.72,1663.78 C37.2@1958.72,1657 1960.72,1655 R220.1@2004.57,1655
NetC43_1: C43.1 R159.2 U27.A4 | length 515.7
  Top Layer w15: v1(1952.5,1077.5) 1969.45,1094.45 1969.45,1144.45 2015,1190 2015,1380.83 2000,1395.83 C43.1@1985,1395.83 1979,1401.83 v2(1979,1419)
  Bottom Layer w12: v2(1979,1419) 1979,1426 1987.86,1434.86 U27.A4@1987.87,1450.04
  Bottom Layer w20: v1(1952.5,1077.5) 1952.5,1057.5 1981.1,1028.9 R159.2@1981.1,999.45
NetC82_1: C82.1 C83.2 CN3.47 CN3.49 R41.2 | length 415.7
  Top Layer w20: 2330.28,2531.12 CN3.49@2352.87,2531.12 ; 2342.29,2312.56 R41.2@2370,2312.56 ; 2352.87,2490.13 CN3.49@2352.87,2531.12 ; 2352.87,2572.11 CN3.49@2352.87,2531.12 ; 2360.8,2370 C82.1@2386.54,2370 ; 2370,2333.18 R41.2@2370,2312.56 ; 2386.54,2334.42 C82.1@2386.54,2370 ; 2386.54,2405.58 C82.1@2386.54,2370 ; 2389.22,2440 C83.2@2407.29,2440 ; 2397.71,2312.56 R41.2@2370,2312.56 ; 2402.87,2490.13 2402.87,2572.11 ; 2407.28,2420.95 C83.2@2407.29,2440 ; 2407.28,2459.05 C83.2@2407.29,2440
NetC82_2: C82.2 C83.1 CN3.45 R43.2 | length 286.1
  Top Layer w20: 2437.29,2312.56 R43.2@2465,2312.56 ; 2442.72,2420.95 C83.1@2442.72,2440 ; 2442.72,2459.05 C83.1@2442.72,2440 ; CN3.45@2452.87,2531.12 2452.87,2477.13 2455,2475 ; 2453.46,2334.42 C82.2@2453.47,2370 ; 2453.46,2405.58 C82.2@2453.47,2370 ; 2460.78,2440 C83.1@2442.72,2440 ; 2465,2333.18 R43.2@2465,2312.56 ; 2479.2,2370 C82.2@2453.47,2370 ; 2492.71,2312.56 R43.2@2465,2312.56
NetC115_2: C115.2 U17.F13 | length 50.2
  Top Layer w10: v2(5087.42,962.43) 5104.86,945 C115.2@5112.29,945
  Bottom Layer w10: U17.F13@5074.65,975.24 v2(5087.42,962.43)
NetC116_2: C116.2 U17.M10 | length 130.8
  Top Layer w5: v2(5010.65,1141.57) 5029.83,1122.39 5104.67,1122.39 C116.2@5112.29,1130
  Bottom Layer w5: U17.M10@4997.88,1128.78 v2(5010.65,1141.57)
NetC121_2: C121.2 U17.J14 | length 145.5
  Bottom Layer w5: U17.J14@5100.24,1052.01 5112.99,1064.77 5130.85,1064.77 5151.08,1085 5187.68,1085 5218.97,1116.29 C121.2@5218.98,1116.42
NetC122_2: C122.2 R110.2 TP2.1 | length 102.3
  Bottom Layer w5: C122.2@5252.72,1020 R110.2@5252.72,975 TP2.1@5310,975
NetC126_2: C126.2 D1.2 D2.2 U19.3 U19.5 | length 482.8
  Bottom Layer w20: 4586.86,1504.88 D2.2@4605.51,1504.88 ; 4605.51,1475.99 D2.2@4605.51,1504.88 ; 4605.51,1533.77 D2.2@4605.51,1504.88 ; 4624.16,1504.88 D2.2@4605.51,1504.88 ; 4651.86,1504.88 D1.2@4670.51,1504.88 ; 4670.51,1475.99 D1.2@4670.51,1504.88 ; 4670.51,1533.77 D1.2@4670.51,1504.88 ; 4689.16,1504.88 D1.2@4670.51,1504.88 ; 4726.31,1502.01 C126.2@4752.05,1502.01 ; 4738.28,1603.7 U19.3@4758.11,1603.7 ; 4752.05,1466.43 C126.2@4752.05,1502.01 ; 4752.05,1537.59 C126.2@4752.05,1502.01 ; 4758.11,1570.09 U19.3@4758.11,1603.7 ; U19.5@4832.92,1690.32 4832.91,1670 4812.91,1650 4776.41,1650 4776.14,1649.73 4770.53,1649.73 4758.11,1637.31 U19.3@4758.11,1603.7
NetC133_2: C133.2 U20.1 | length 73.7
  Bottom Layer w10: C133.2@4510,452.28 4510,450 4556.45,403.55 U20.1@4556.45,397.87
NetC135_2: C135.2 C136.2 L6.2 R132.2 R135.2 R136.1 | length 471.8
  Bottom Layer w20: 3733.2,1017.72 R135.2@3755,1017.72 ; 3755,1035.78 R135.2@3755,1017.72 ; 3776.8,1017.72 R135.2@3755,1017.72 ; 3884.22,1045 R132.2@3902.29,1045 3902.28,1066.8 ; 4080.36,1050.04 L6.2@4175,1050.04 ; 4099.46,1117.44 C136.2@4125,1117.44 ; 4125,1096.82 C136.2@4125,1117.44 ; 4150.54,1117.44 C136.2@4125,1117.44 ; 4169.46,1117.44 C135.2@4195,1117.44 ; 4175,1087.59 L6.2@4175,1050.04 ; 4195,1096.82 C135.2@4195,1117.44 ; 4220.54,1117.44 C135.2@4195,1117.44 ; 4269.64,1050.04 L6.2@4175,1050.04
NetC137_2: C137.2 C138.2 C139.2 R130.2 U22.1 U22.6 | length 215.1
  Bottom Layer w12: C139.2@3808.39,922.13 U22.1@3854.92,922.12 ; U22.6@3971.07,973.3 4015.87,973.31 C137.2@4020,977.44
  Bottom Layer w20: 3808.39,886.61 C139.2@3808.39,922.13 ; v1(4055,960) 4037.44,960 C137.2@4020,977.44 4032.56,990 v1(4055,990)
  other v1: 3813,774 3840,774 3866,774 3893,774
NetC145_2: C145.2 R145.2 U28.1 | length 105.9
  Bottom Layer w15: R145.2@2322.45,945 2322.44,894.84 2331.42,885.86 U28.1@2331.42,842.8
NetC153_2: C153.2 R154.1 X2.3 | length 158.4
  Bottom Layer w5: X2.3@2085.67,1105.24 2107.5,1105.24 2112.5,1110.24 2112.5,1179.78 C153.2@2097.29,1195 2097.28,1229.56 R154.1@2100,1232.28
NetC154_1: C154.1 U34.27 | length 78.1
  Bottom Layer w5: U34.27@2095.43,431.59 2161.59,431.59 C154.1@2170,440
NetC155_2: C155.2 R155.1 X2.1 | length 112.9
  Bottom Layer w5: X2.1@2044.34,1134.76 2044.33,1154.07 2057.72,1167.46 2057.72,1227.28 2052.72,1232.28 R155.1@2045,1232.28
NetC156_1: C156.1 U34.24 | length 114.9
  Bottom Layer w5: U34.24@2074.76,483.76 2074.76,495.31 2084.46,505 2110,505 2120,495 C156.1@2170,495
NetC158_1: C158.1 R156.2 U34.20 | length 234.4
  Bottom Layer w7: R156.2@1940,670 1955,670 1961.5,663.5 1961.5,573.5 1970,565 C158.1@1995,565 ; C158.1@1995,560 1995,540 2011.5,523.5 2011.5,484.03 U34.20@2011.77,483.76
NetC160_1: C160.1 U34.10 | length 150.9
  Bottom Layer w7: C160.1@1837.44,300 1837.44,327.44 1843.98,333.98 1868.68,333.98 1903.3,368.6 U34.10@1943.86,368.6
NetC160_2: C160.2 U34.8 | length 93.4
  Bottom Layer w5: C160.2@1892.56,300 1915,300 1925,310 1956.12,310 1964.53,318.41 U34.8@1964.53,332.18
NetC162_2: C162.2 SB39.2 SB40.2 U34.19 | length 293.9
  Bottom Layer w7: 1985,525 1996.02,513.98 U34.19@1996.02,483.76
  Bottom Layer w10: 1804.69,615 SB40.2@1870,615 ; SB40.2@1870,613.27 1870,585 1895,560 C162.2@1940,560 1940,535 1950,525 1985,525
NetC163_1: C163.1 U34.11 | length 101.4
  Bottom Layer w7: C163.1@1852.56,360 1870,360 1894.35,384.35 U34.11@1943.86,384.35
NetC164_1: C164.1 CN15.4 U34.15 U42.6 | length 2047.5
  Bottom Layer w7: 1070,560 1110,600 1350,600 1385,565 1475,565 1521.5,611.5 1563.5,611.5 1587.4,587.6 U42.6@1587.4,549.78 1617.18,520 1820,520 1830.43,530.43 C164.1@1830.43,550 1850,550 1855,545 1855,520 1927.66,447.34 U34.15@1943.86,447.34
  Bottom Layer w9: 1070,560 1070,240 1055,225 1055,155 1100,110 1225,110 1240,125 1240,245 1280,285 1325,285 1365,245 1441.66,245 CN15.4@1441.66,238.66
NetC164_2: C164.2 R164.2 | length 42.4
  Bottom Layer w8: R164.2@1752.56,550 C164.2@1795,550
NetC165_1: C165.1 CN15.6 U34.13 U42.1 | length 935.2
  Bottom Layer w7: CN15.6@1170.01,530 1205.01,565 1335,565 1480,420 1580,420 1587.4,427.4 U42.1@1587.4,459.22 1616.18,488 1837,488 1842.72,482.28 C165.1@1842.72,465 1865,465 1914.16,415.84 U34.13@1943.86,415.84
NetC165_2: C165.2 R165.2 | length 63.9
  Bottom Layer w9: R165.2@1747.56,455 1772.42,455 1782.42,465 C165.2@1807.28,465
NetC167_1: C167.1 U34.12 | length 98.3
  Bottom Layer w7: C167.1@1852.56,415 1853.56,416 1882.8,416 1898.7,400.1 U34.12@1943.86,400.1
NetC168_2: C168.2 U34.21 | length 88.8
  Bottom Layer w7: U34.21@2027.52,483.76 2027.52,511.32 2026.5,512.34 2026.5,538.94 C168.2@2050,562.44
NetC171_2: C171.2 C172.2 R163.1 U43.1 | length 214.1
  Bottom Layer w5: 1618.27,988.27 U43.1@1618.27,972.28 1627.29,972.29 1630,975
  Bottom Layer w20: 1640.95,977.72 C172.2@1660,977.72 ; 1660,995.78 C172.2@1660,977.72 ; 1679.05,977.72 C172.2@1660,977.72 ; 1685.8,1040 R163.1@1710.55,1040 ; 1690.95,977.72 C171.2@1710,977.72 1710,995.78 ; 1710.55,1006.39 R163.1@1710.55,1040 ; 1710.55,1073.61 R163.1@1710.55,1040
NetC174_2: C174.2 R170.1 X3.1 | length 109.2
  Bottom Layer w5: X3.1@1555.39,1434.16 1557.64,1436.41 1628.92,1436.41 1631.2,1438.69 R170.1@1662.68,1438.69
NetC175_2: C175.2 R171.1 X3.2 | length 109.2
  Bottom Layer w5: X3.2@1555.39,1493.22 1557.64,1490.97 1628.92,1490.97 1631.2,1488.69 R171.1@1662.68,1488.69
NetC184_1: C184.1 Q3.7 Q3.8 Q4.7 Q4.8 R7.1 R209.2 U46.10 | length 705.8
  Top Layer w10: R7.1@958.45,1415 962,1415 972,1405 972,1238 990,1220 1020,1220 v1(1027.5,1227.5)
  Top Layer w20: 938.5,1378.5 958.45,1398.45 R7.1@958.45,1415 958.45,1469.45
  Bottom Layer w10: U46.10@1005.39,1201.49 1005.38,1205.38 v1(1027.5,1227.5)
  Bottom Layer w20: 750,1552.68 Q4.7@750,1585.31 770.82,1585.31 ; 779.18,1585.31 Q4.8@800,1585.31 ; 800,1552.68 Q4.8@800,1585.31 ; 820.82,1585.31 Q4.8@800,1585.31 ; 1021.01,1552.17 Q3.7@1021.01,1584.8 ; 1021.01,1617.43 Q3.7@1021.01,1584.8 ; 1041.83,1584.8 Q3.7@1021.01,1584.8 ; 1050.19,1584.8 Q3.8@1071.01,1584.8 ; 1071.01,1552.17 Q3.8@1071.01,1584.8 ; 1071.01,1617.43 Q3.8@1071.01,1584.8 ; 1091.83,1584.8 Q3.8@1071.01,1584.8
  other v1: 830,1550 855,1550 1125,1565 1150,1565 830,1580 855,1580 1125,1590 1150,1590 830,1610 855,1610 1125,1620 1150,1620
NetC184_2: C184.2 Q3.2 Q3.4 R228.1 U46.7 | length 607.1
  Top Layer w20: v1(1021.01,1328.99) 1138.99,1328.99 1168.36,1358.36 v1(1168.36,1395)
  L3_SIG w20: v1(920,1328.99) v1(1021.01,1328.99)
  Bottom Layer w10: 940,1240 946.33,1233.67 U46.7@946.33,1201.49
  Bottom Layer w20: Q3.4@921.01,1374.17 921.01,1330 v1(920,1328.99) 927.28,1321.71 R228.1@927.28,1290 927.28,1252.72 940,1240 ; v1(1021.01,1328.99) Q3.2@1021.01,1374.17 ; C184.2@1160,1472.28 1160,1403.36 v1(1168.36,1395)
NetC185_1: C185.1 U46.14 | length 73.5
  Bottom Layer w5: U46.14@1041.8,1106.01 1060.21,1106.01 1071.22,1095 1082.44,1095 C185.1@1102.45,1075
NetC186_2: C186.2 CN18.A5 U46.15 | length 1030.9
  Top Layer w5: v1(390,1030) 450,970 605,970 675,1040 813.38,1040 868.38,985 v1(1085,985)
  Bottom Layer w5: CN18.A5@315.4,1054.41 350.59,1054.41 375,1030 v1(390,1030) ; U46.15@1041.8,1086.33 1058.67,1086.33 1070,1075 1070,1050 1095,1025 C186.2@1112.29,1025 1112.28,1012.28 v1(1085,985) ; 1112.29,1012.29 C186.2@1112.29,1025
NetC187_2: C187.2 CN18.B5 U46.13 | length 982.1
  Top Layer w5: v1(285,1110) 385,1210 935,1210 949.5,1195.5 1004.5,1195.5 v1(1080,1120)
  Bottom Layer w5: CN18.B5@248.47,1103.62 278.62,1103.62 v1(285,1110) ; U46.13@1041.8,1125.7 v1@1075,1125.7 ; v1(1080,1120) 1089,1129 C187.2@1112.29,1129
NetC188_2: C188.2 R198.1 X4.1 | length 218.6
  Bottom Layer w5: X4.1@1013.31,2678.5 970,2721.81 970,2771.73 1035,2836.73 R198.1@1035,2852.28
NetC191_2: C191.2 R205.1 X4.3 | length 122.5
  Bottom Layer w5: X4.3@926.7,2741.5 952.72,2767.53 952.72,2850 R205.1@955,2852.28
NetC193_2: C193.2 CN16.5 CN16.6 | length 239.6
  Bottom Layer w10: CN16.6@542.49,3041.8 592.47,2991.8 CN16.5@642.49,2991.8 739.52,2991.8 C193.2@755,3007.28
NetC196_2: C196.2 Q4.2 Q4.4 R229.1 U46.5 | length 698.4
  Top Layer w20: v1(590,1330) v1(750,1330)
  Bottom Layer w10: 840,1180 854.93,1165.07 U46.5@890.23,1165.07
  Bottom Layer w20: Q4.4@650,1374.68 607.25,1374.69 605,1372.44 600,1372.44 590,1362.44 v1(590,1330) 615,1330 R229.1@660.28,1284.72 ; R229.1@660.28,1286 R229.1@660.28,1284.72 ; v1(750,1330) Q4.2@750,1374.68 ; 840,1180 720,1180 660.28,1239.72 R229.1@660.28,1284.72
NetC200_2: C200.2 SB53.1 U54.2 U54.4 | length 250
  Bottom Layer w30: U54.4@2618.91,3234.3 U54.2@2618.91,3484.3
NetCN1_5: CN1.5 SB1.2 | length 160.1
  Top Layer w5: SB1.2@100,3626.38 136.38,3590 CN1.5@245.02,3590
NetCN1_9: CN1.9 R5.1 SB2.1 | length 278
  Top Layer w5: CN1.9@295.02,3740 358.56,3740 442.29,3823.73 R5.1@442.29,3845 436.71,3850.58 SB2.1@436.71,3905 436.71,3892.5
NetCN3_24: CN3.24 SB5.1 | length 110
  Top Layer w5: CN3.24@3002.87,2676.22 3002.87,2783.19 SB5.1@3005,2785.32
NetCN3_38: CN3.38 R69.1 | length 91.9
  Top Layer w5: CN3.38@2652.87,2676.22 2652.87,2765.15 R69.1@2655,2767.28
NetCN3_40: CN3.40 R68.1 | length 92.2
  Top Layer w5: R68.1@2600,2767.28 2602.87,2764.41 CN3.40@2602.87,2676.22
NetCN6_A5: CN6.A5 R96.2 R108.1 | length 295
  Top Layer w5: v1(5390,1330) 5390,1302.72 R96.2@5392.72,1300
  Bottom Layer w5: v1(5390,1330) R108.1@5390,1302.72 ; R108.1@5392.72,1300 R108.1@5390,1302.72 ; CN6.A5@5585.95,1240.7 5545,1240.7 5533.7,1252 5483,1252 5465,1270 5403.78,1270 5390,1283.78 R108.1@5390,1302.72
NetCN6_B5: CN6.B5 R97.2 R107.1 | length 337.2
  Top Layer w5: R97.2@5393.23,1127.01 5422.99,1127.01 v1(5425,1125) 5445,1105 5536.24,1105 v1(5616.35,1185.11)
  Bottom Layer w5: R107.1@5393.23,1127.01 5422.99,1127.01 v1(5425,1125) ; v1(5616.35,1185.11) 5622.73,1191.49 CN6.B5@5652.88,1191.49
NetCN8_1: CN8.1 R111.1 | length 244.8
  Bottom Layer w15: R111.1@5127.72,3135 CN8.1@5372.5,3135
NetCN10_11: CN10.11 CN10.13 SB54.2 | length 436.9
  Bottom Layer w20: CN10.13@3785.76,297.01 3872.99,297.01 ; CN10.11@3785.76,347.01 3872.99,347.01 3872.99,297.01 ; SB54.2@3968.33,150 3935,150 3917,168 3917,264 3883.99,297.01 3872.99,297.01
NetCN12_8: CN12.8 R137.1 | length 141.1
  Bottom Layer w20: CN12.8@3472.48,3295 3610.78,3295 R137.1@3612.8,3297.01
NetCN16_11: CN16.11 R219.1 | length 218.2
  Bottom Layer w5: CN16.11@132.64,2755.78 132.63,2675.11 R219.1@229.92,2577.83
NetCN16_12: CN16.12 R191.2 U44.32 | length 1295.1
  Top Layer w5: CN16.12@132.64,2855.78 161.86,2885 415,2885 565,2735 795,2735 868,2808 896.03,2808 915.03,2789 1009.91,2789 1026.21,2805.3 1026.21,2840 1078.21,2892 1117.13,2892 1132.69,2907.56 1132.69,2907.69 v1(1138.86,2913.86)
  Bottom Layer w5: U44.32@1097.75,2956.37 1097.75,2942.26 1109.02,2930.99 1122.44,2930.99 1132.69,2920.74 1132.69,2920.03 v1(1138.86,2913.86) R191.2@1165,2887.72
NetCN16_13: CN16.13 R195.2 U44.33 | length 1350.4
  Top Layer w5: CN16.13@132.64,3177.82 385.46,2925 405,2925 580,2750 785,2750 856,2821 904.25,2821 923.25,2802 997,2802 1010,2815 1010,2845.01 1078.48,2913.49 v1(1111,2913.49)
  Bottom Layer w5: U44.33@1082.01,2956.37 1082,2936 1103,2915 1112.34,2915 1111,2913.66 v1(1111,2913.49) 1111.47,2913.96 1114.72,2913.96 1120,2908.68 R195.2@1120,2887.72
NetCN16_14: CN16.14 R218.2 | length 227.4
  Bottom Layer w5: 132.63,3314.87 132.63,3360.55 R218.2@234.92,3462.83 ; CN16.14@132.64,3277.82 132.64,3314.86
NetD4_1: D4.1 R140.1 U25.A4 | length 206.5
  Bottom Layer w5: D4.1@2942.64,1832.01 2944.38,1830.27 R140.1@3005.09,1830.27 3005.08,1945.07 U25.A4@2984.88,1965.27
NetD5_1: D5.1 D6.1 R144.2 U28.3 | length 209.1
  Bottom Layer w5: U28.3@2382.61,842.8 2382.6,827.4 2392.79,817.21 2467.6,817.21 D6.1@2492.01,841.62 D5.1@2562.01,841.62
NetD7_1: D7.1 R207.2 U44.12 | length 180.8
  Bottom Layer w5: D7.1@877.13,3255 927.28,3255 987.52,3194.76 U44.12@987.52,3149.29
NetL3_1: L3.1 U1.7 | length 266.8
  Top Layer w15: 1322.8,1852.8 U1.7@1322.8,1881.93 1322.8,1892.69 1322.87,1892.76
  Top Layer w20: 1275.36,1750.04 L3.1@1370,1750.04 ; 1370,1787.59 L3.1@1370,1750.04 ; 1464.64,1750.04 L3.1@1370,1750.04
NetL5_1: L5.1 U2.B2 | length 184.1
  Top Layer w10: U2.B2@1840,3334.25 1840.25,3334 1864.6,3334
  Top Layer w19: 1864.6,3334.25 L5.1@2020,3334.25
  Top Layer w19.5: L5.1@2020,3334.1 L5.1@2024,3334.1
NetL6_1: L6.1 U22.7 | length 315.7
  Bottom Layer w12: U22.7@3971.07,947.71 3997.29,947.71 4015,930
  Bottom Layer w20: 4080.36,929.96 L6.1@4175,929.96 ; 4175,892.41 L6.1@4175,929.96 ; 4175,967.51 L6.1@4175,929.96 ; 4269.64,929.96 L6.1@4175,929.96
NetL7_2: L7.2 R220.2 U27.J1 U27.J2 U27.J3 U27.J4 U27.J5 U27.J6 | length 472.9
  Top Layer w15: R220.2@2040,1655 2060,1655 2071.68,1666.68 2074.61,1666.68 v2@2092,1684.07 ; v2(2092,1685) 2092.19,1685.19 2092.19,1703.92 2093,1704.73 v2(2093,1705)
  Bottom Layer w15: U27.J1@1893.38,1702.01 1901.37,1710 1916.89,1710 U27.J2@1924.88,1702.01 1932.87,1710 1948.38,1710 U27.J3@1956.37,1702.01 1963.36,1709 1980.88,1709 U27.J4@1987.87,1702.01 1993.86,1708 2013.37,1708 U27.J5@2019.36,1702.01 2025.35,1708 2044.87,1708 U27.J6@2050.86,1702.01 2060.85,1712 2086,1712 v2(2093,1705) 2093,1686 v2(2092,1685)
  Bottom Layer w20: 1743,1740 1738,1735 1726.12,1732.28 L7.2@1725.5,1732.14 ; 1749,1770 1725.5,1746.5 L7.2@1725.5,1735 L7.2@1725.5,1732.14 ; 1762,1709 1738,1709 1725.5,1721.5 L7.2@1725.5,1725.5 ; L7.2@1725.5,1725.5 1720.77,1730.7 1720.5,1731 L7.2@1725.5,1732.14 ; L7.2@1725.5,1725.5 L7.2@1725.5,1732.14
  other v2: 1854,1685 1876.37,1685
NetLD1_2: LD1.2 R1.2 | length 146
  Top Layer w5: R1.2@59.3,589.49 59.29,610.77 60.47,611.95 LD1.2@60.48,735
NetLD2_2: LD2.2 R2.2 | length 56.1
  Top Layer w5: LD2.2@241.18,735 R2.2@297.29,735
NetLD3_1: LD3.1 R98.1 | length 65.7
  Top Layer w5: R98.1@5585.44,1500 5585.91,1500.47 LD3.1@5650.95,1500.47
NetLD3_2: LD3.2 R99.1 | length 65.7
  Top Layer w5: R99.1@5585.44,1560 5585.91,1559.53 LD3.2@5650.95,1559.53
NetLD4_1: LD4.1 R100.1 | length 65.7
  Top Layer w5: R100.1@5585.44,1665 5585.91,1665.47 LD4.1@5650.95,1665.47
NetLD4_2: LD4.2 R101.2 | length 65.7
  Top Layer w5: R101.2@5585.44,1725 5585.91,1724.53 LD4.2@5650.95,1724.53
NetLD5_1: LD5.1 R129.2 | length 64.4
  Bottom Layer w20: R129.2@4282.21,606.64 4346.22,606.64 LD5.1@4346.49,606.38
NetLD6_1: LD6.1 R131.1 | length 63.1
  Bottom Layer w5: LD6.1@3900.48,3015 3900.47,2969.33 R131.1@3912.8,2957.01
NetLD6_2: LD6.2 Q2.3 | length 101.9
  Bottom Layer w5: LD6.2@3959.53,3015 3965.32,3020.79 Q2.3@3965.32,3114.49
NetLD7_1: LD7.1 R194.2 U44.34 | length 270.9
  Bottom Layer w5: U44.34@1066.25,2956.37 1066.25,2930.89 1096.28,2900.86 1096.28,2779.19 LD7.1@1115.48,2760 1115.47,2712.25 R194.2@1120,2707.72
NetLD7_2: LD7.2 R190.2 | length 52.5
  Bottom Layer w5: LD7.2@1174.53,2760 1174.53,2708.19 R190.2@1175,2707.72
NetLD8_2: LD8.2 R211.2 | length 52.8
  Bottom Layer w20: R211.2@897.72,1950 LD8.2@950.47,1950
NetLD9_1: LD9.1 R212.2 | length 62.6
  Bottom Layer w20: LD9.1@484,1466.41 524.13,1466.41 R212.2@540,1482.28
NetLD9_2: LD9.2 Q5.3 | length 110.7
  Bottom Layer w20: Q5.3@379.01,1539.25 439.47,1539.25 453.25,1525.47 LD9.2@484,1525.47
NetLD10_2: LD10.2 R217.2 | length 80.2
  Bottom Layer w20: R217.2@272.72,1545 272.72,1548.74 299.48,1575.5 299.48,1600.05 LD10.2@289.53,1610
NetLE1_1: LE1.1 U44.30 | length 223.6
  Bottom Layer w8: U44.30@1139.09,2981.96 1148.84,2981.96 1155.46,2975.34 1155.46,2959.54
  Bottom Layer w20: 1155.46,2959.54 1175,2940 1283.31,2940 1310,2913.31 LE1.1@1325,2913.31
NetQ1_1: Q1.1 R3.2 R4.1 | length 128.5
  Top Layer w5: Q1.1@243.82,549.61 292.33,549.61 R3.2@310,567.28 R4.1@365,567.28
NetQ1_3: Q1.3 R1.1 | length 63.5
  Top Layer w5: R1.1@94.73,589.49 154.72,589.49 Q1.3@157.21,587.01
NetQ2_1: Q2.1 R134.2 SB25.2 | length 217.5
  Bottom Layer w5: SB25.2@3668.64,3095 3783.78,3095 R134.2@3787.01,3091.77 3864.02,3091.77 Q2.1@3878.71,3077.09
NetQ3_1: Q3.1 Q3.3 R228.2 U46.8 | length 355.9
  Bottom Layer w10: U46.8@966.02,1201.49 966.01,1246.01 971.01,1251.01
  Bottom Layer w20: 971.01,1251.01 962.72,1259.3 R228.2@962.72,1290 ; Q3.3@971.01,1374.17 971.01,1325 962.72,1316.71 R228.2@962.72,1290 ; Q3.1@1071.01,1374.17 1071.01,1321.01 1040,1290 R228.2@962.72,1290
NetQ4_1: Q4.1 Q4.3 R229.2 U46.6 | length 455.1
  Bottom Layer w10: 915.01,1220 926.64,1208.37 U46.6@926.64,1201.49
  Bottom Layer w20: Q4.3@700,1374.68 700,1325 695.72,1320.72 R229.2@695.72,1286 701.72,1280 800,1280 ; Q4.1@800,1374.68 800,1280 ; 915.01,1220 860,1220 800,1280
NetQ5_1: Q5.1 R213.2 R214.1 | length 135.5
  Bottom Layer w20: Q5.1@416.41,1452.63 419.75,1449.28 419.75,1420.98 416.56,1417.79 R214.1@416.56,1375.94 446.3,1375.94 447.24,1375 R213.2@472.29,1375
NetQ6_1: Q6.1 R215.2 R216.1 | length 100.6
  Bottom Layer w20: Q6.1@187.41,1451.69 235.59,1451.69 R215.2@237.29,1450 R216.1@237.29,1500
NetQ6_3: Q6.3 R217.1 | length 90.1
  Bottom Layer w20: Q6.3@150.01,1538.31 184.69,1538.31 191.38,1545 R217.1@237.29,1545
NetQ7_1: Q7.1 R158.2 | length 55
  Top Layer w5: R158.2@1606.3,3192.92 1613.29,3192.92 Q7.1@1647.22,3158.99
NetQ7_3: Q7.3 R157.1 | length 77.5
  Top Layer w5: R157.1@1620,3247.28 1620,3226.9 1644.6,3202.3 Q7.3@1666.9,3202.3
NetR8_1: R8.1 U1.5 | length 68.3
  Top Layer w10: R8.1@1220,1922.28 1260.35,1881.93 U1.5@1271.62,1881.93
